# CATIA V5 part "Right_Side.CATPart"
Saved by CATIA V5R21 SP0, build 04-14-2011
Part number: Left_Side
Bounding box of the stored display mesh (mm): x -172.8 to 2.8, y 0 to 2.8, z -5 to 133.511
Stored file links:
  C:\Users\Pouria\Desktop\Box\Right_Side.CATPart
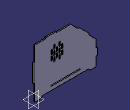
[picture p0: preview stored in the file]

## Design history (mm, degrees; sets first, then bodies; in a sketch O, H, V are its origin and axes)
Body1 (main body)
  Sketch1 on zx-plane, origin (0, 0, 0), H (-1, 0, 0), V (0, 0, 1)
    line L1 (0, 0) -> (0, 40)
    line L2 (0, 130.7107) -> (30, 130.7107)
    point P2 (99.2893, 130.7107)
    line L3 (99.2893, 130.7107) -> (120.5025, 109.4975)
    point P3 (170, 60)
    line L4 (170, 60) -> (170, 40)
    point P4 (170, 0)
    line L5 (147.8, 0) -> (22.2, 0)
    line L6 (45, 12.8) -> (125, 12.8)
    line L7 (125, 12.8) -> (125, 10)
    line L8 (125, 10) -> (45, 10)
    line L9 (45, 10) -> (45, 12.8)
    line L10 (147.8, 0) -> (152.8, -5)
    line L11 (152.8, -5) -> (170, -5)
    point P11 (170, -5)
    line L12 (170, -5) -> (170, 0)
    line L13 (0, 0) -> (0, -5)
    line L14 (0, -5) -> (17.2, -5)
    line L15 (17.2, -5) -> (22.2, 0)
    circle A1 centre (14, 106.7107) radius 1.5
    point P15 (14, 106.7107)
    circle A2 centre (14, 74.7107) radius 1.5
    point P16 (14, 74.7107)
    circle A3 centre (86, 106.7107) radius 1.5
    point P17 (86, 106.7107)
    circle A4 centre (86, 74.7107) radius 1.5
    point P18 (86, 74.7107)
    line L16 (120.5025, 109.4975) -> (122.4824, 111.4774)
    line L17 (122.4824, 111.4774) -> (150.7667, 83.1931)
    line L18 (150.7667, 83.1931) -> (148.7868, 81.2132)
    point P22 (148.7868, 81.2132)
    line L19 (148.7868, 81.2132) -> (170, 60)
    line L20 (30, 130.7107) -> (30, 133.5107)
    line L21 (30, 133.5107) -> (60, 133.5107)
    line L22 (60, 133.5107) -> (60, 130.7107)
    point P26 (60, 130.7107)
    line L23 (170, 40) -> (172.8, 40)
    line L24 (172.8, 40) -> (172.8, 20)
    line L25 (172.8, 20) -> (170, 20)
    point P30 (170, 20)
    line L26 (170, 20) -> (170, 0)
    line L27 (60, 130.7107) -> (99.2893, 130.7107)
    point P31 (0, 90)
    line L28 (0, 90) -> (-2.8, 90)
    line L29 (-2.8, 90) -> (-2.8, 40)
    line L30 (-2.8, 40) -> (0, 40)
    line L31 (0, 90) -> (0, 130.7107)
    length L6 = 80
    distance L8 L6 = 2.8
    distance L7 L4 = 45
    distance L8 L5 = 10
    angle L3 L4 = 135
    angle L10 L5 = 45
    length L12 = 5
    length L11 = 17.2
    length L14 = 17.2
    length L13 = 5
    angle L5 L15 = 45
    distance P4 O = 170
    length L5 = 125.6
    distance P18 P17 H = 0
    distance P16 P15 H = 0
    distance P17 P15 V = 0
    distance P18 P16 V = 0
    distance P18 P16 = 72
    distance P15 P16 = 32
    radius A1 = 1.5
    radius A3 = 1.5
    radius A4 = 1.5
    radius A2 = 1.5
    distance P15 L2 = 24
    distance P15 L1 = 14
    length L17 = 40
    distance L17 L3 = 2.8
    distance L18 P3 = 30
    distance P2 P3 = 100
    length L24 = 20
    length L23 = 2.8
    distance L25 L5 = 20
    distance P3 P4 = 60
    length L21 = 30
    distance L20 L1 = 30
    distance L21 L2 = 2.8
    length L29 = 50
    distance L5 L30 = 40
    distance L29 L1 = 2.8
    vertical: L1 V, L4 V, L7 V, L9 V, L12 V, L13 V, L20 V, L22 V, L24 V, L26 V, L29 V, L31 V
    horizontal: L2 H, L5 H, L6 H, L8 H, L11 H, L14 H, L21 H, L23 H, L25 H, L27 H, L28 H, L30 H
    coincidence: P4 H, P11 L4, L12 L4, L13 L1, P22 L3, L3 L19, P26 L2, P30 L4, L4 L26, L2 L27, P31 L1, L1 L31
    perpendicularity: L18 L3, L16 L3
  Pad1: profile Sketch1, direction (0, 1, 0), length 2.8
  Sketch2 on end face of Pad1, origin (0, 2.8, 0), H (-1, 0, 0), V (0, 0, 1)
    line L1 (77.5, 81.7107) -> (73.5, 81.7107)
    line L2 (73.5, 81.7107) -> (73.5, 69.7107)
    line L3 (73.5, 69.7107) -> (77.5, 69.7107)
    line L4 (77.5, 69.7107) -> (77.5, 81.7107)
    reference projected circle E1 centre (86, 74.7107) radius 1.5 from edge [end face of Pad1 | face of Pad1 from Sketch1.A4]
    reference projected circle E2 centre (86, 74.7107) radius 1.5 from edge [end face of Pad1 | face of Pad1 from Sketch1.A4]
    distance L3 E1 = 3.5
    distance L4 E2 = 10
    length L3 = 4
    length L2 = 12
    horizontal: L1 H, L3 H
    vertical: L2 V, L4 V
  Pocket1: profile Sketch2, direction (0, -1, 0), through (limit type 3)
  RectPattern1: of Pocket1, direction 1 instances 3, spacing 14, along edge [end face of Pad1 | face of Pad1 from Sketch1.L6], direction 2 instances 3, spacing 15, along edge [face of Pad1 from Sketch1.L29 | end face of Pad1] reversed
  Sketch3 on end face of Pad1, origin (0, 2.8, 0), H (-1, 0, 0), V (0, 0, 1)
    line L1 (66.5, 75.7107) -> (70.5, 75.7107)
    line L2 (70.5, 75.7107) -> (70.5, 63.7107)
    line L3 (70.5, 63.7107) -> (66.5, 63.7107)
    line L4 (66.5, 63.7107) -> (66.5, 75.7107)
    reference projected line E1 (73.5, 81.7107) -> (73.5, 69.7107) from edge [end face of Pad1 | face of Pocket1 from Sketch2.L2]
    reference projected line E2 (73.5, 69.7107) -> (77.5, 69.7107) from edge [end face of Pad1 | face of Pocket1 from Sketch2.L3]
    distance L2 E1 = 3
    length L2 = 12
    length L3 = 4
    distance L3 E2 = 6
    horizontal: L1 H, L3 H
    vertical: L2 V, L4 V
  Pocket2: profile Sketch3, direction (0, -1, 0), through (limit type 3)
  RectPattern2: of Pocket2, direction 1 instances 2, spacing 14, along edge [face of Pad1 from Sketch1.L27 | end face of Pad1], direction 2 instances 3, spacing 15, along edge [face of Pad1 from Sketch1.L31 | end face of Pad1] reversed
  Fillet1: radius 1, on edge [face of RectPattern1 | face of RectPattern1] (x32); edge [face of RectPattern2 | face of RectPattern2] (x20); edge [face of Pocket1 from Sketch2.L2 | face of Pocket1 from Sketch2.L1]; edge [face of Pocket2 from Sketch3.L4 | face of Pocket2 from Sketch3.L1]; edge [face of Pocket2 from Sketch3.L3 | face of Pocket2 from Sketch3.L4]; edge [face of Pocket1 from Sketch2.L3 | face of Pocket1 from Sketch2.L2]; edge [face of Pocket1 from Sketch2.L1 | face of Pocket1 from Sketch2.L4]; edge [face of Pocket2 from Sketch3.L1 | face of Pocket2 from Sketch3.L2]; edge [face of Pocket2 from Sketch3.L2 | face of Pocket2 from Sketch3.L3]; edge [face of Pocket1 from Sketch2.L4 | face of Pocket1 from Sketch2.L3]
  Sketch4 on end face of Pad1, origin (0, 2.8, 0), H (-1, 0, 0), V (0, 0, 1)
    line L1 (78.7193, 113.3506) -> (72.6493, 113.3506)
    line L2 (72.6493, 113.3506) -> (72.6493, 98.8904)
    line L3 (72.6493, 98.8904) -> (78.7193, 98.8904)
    line L4 (78.7193, 98.8904) -> (78.7193, 113.3506)
    point P5 (64.9239, 113.3506)
    line L5 (64.9239, 113.3506) -> (58.0813, 113.3506)
    line L6 (58.0813, 113.3506) -> (58.0813, 98.8904)
    line L7 (58.0813, 98.8904) -> (64.9239, 98.8904)
    line L8 (64.9239, 98.8904) -> (64.9239, 113.3506)
    point P7 (58.0813, 98.8904)
    line L9 (50.4662, 112.7031) -> (43.8443, 112.7031)
    line L10 (43.8443, 112.7031) -> (43.8443, 98.8904)
    line L11 (43.8443, 98.8904) -> (50.4662, 98.8904)
    line L12 (50.4662, 98.8904) -> (50.4662, 112.7031)
    point P11 (43.8443, 98.8904)
    horizontal: L1 H, L3 H, L5 H, L7 H, L9 H, L11 H
    vertical: L2 V, L4 V, L6 V, L8 V, L10 V, L12 V
    coincidence: P5 L1, P7 L3, P11 L3
  Pad2: profile Sketch4, direction (0, 1, 0), up to start face of Pad1
  Sketch5 on face of Pad1, origin (0, 2.8, 0), H (-1, 0, 0), V (0, 0, 1)
    line L1 (80.254, 113.5832) -> (93.061, 113.5832)
    line L2 (93.061, 113.5832) -> (93.061, 67.4862)
    line L3 (93.061, 67.4862) -> (80.254, 67.4862)
    line L4 (80.254, 67.4862) -> (80.254, 113.5832)
    point P5 (7.4953, 113.5832)
    line L5 (7.4953, 113.5832) -> (20.1167, 113.5832)
    line L6 (20.1167, 113.5832) -> (20.1167, 65.1269)
    line L7 (20.1167, 65.1269) -> (7.4953, 65.1269)
    line L8 (7.4953, 65.1269) -> (7.4953, 113.5832)
    horizontal: L1 H, L3 H, L5 H, L7 H
    vertical: L2 V, L4 V, L6 V, L8 V
    coincidence: P5 L1
  Pad3: profile Sketch5, direction (0, 1, 0), up to face of Pad1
